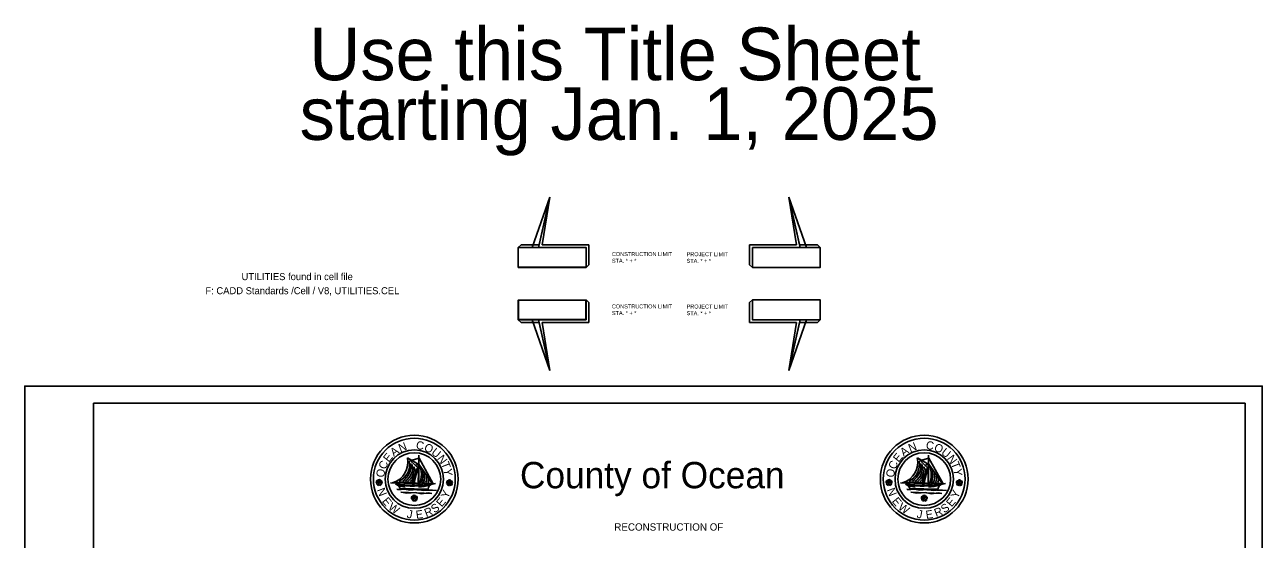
# Model space of a CAD drawing. Extents: x -51896 to -50062, y 9316 to 10514.
# Drawn here: x -51896 to -50816, y 10064 to 10514 of the extents above; entities that cross this region are included whole.
import ezdxf

# ---------------------------------------------------------------- set-up
doc = ezdxf.new("R2010")
doc.units = 0
for name, color, linetype in [('_Guidelines', 7, 'Continuous'), ('Level 1', 7, 'Continuous'), ('Level 47', 7, 'Continuous'), ('Level 60', 7, 'Continuous')]:
    doc.layers.add(name, color=color, linetype=linetype)

msp = doc.modelspace()

# ---------------------------------------------------------------- linework, layer by layer
at = {"layer": '_Guidelines'}
msp.add_lwpolyline([(-51895.6, 9478.3), (-50815.6, 9478.3), (-50815.6, 10198.3), (-51895.6, 10198.3)], close=True, dxfattribs=at)
at = {"layer": 'Level 1'}
for p, q in [((-51452.8, 10319.3), (-51437.3, 10363.4)), ((-51437.3, 10363.4), (-51447.3, 10319.3)), ((-51437.3, 10363.4), (-51446.7, 10321.7)), ((-51444, 10321.7), (-51437.3, 10363.4)), ((-51222.2, 10321.7), (-51228.9, 10363.4)), ((-51228.9, 10363.4), (-51219.5, 10321.7)), ((-51213.4, 10319.3), (-51228.9, 10363.4)), ((-51228.9, 10363.4), (-51218.9, 10319.3)), ((-51462.4, 10321.7), (-51464.9, 10319.3)), ((-51464.9, 10319.3), (-51405.6, 10319.3)), ((-51446.7, 10321.7), (-51462.4, 10321.7)), ((-51447.3, 10319.3), (-51452.8, 10319.3)), ((-51403.2, 10321.7), (-51444, 10321.7)), ((-51405.6, 10319.3), (-51405.6, 10301.9)), ((-51403.2, 10304.3), (-51403.2, 10321.7)), ((-51263.1, 10304.3), (-51263.1, 10321.7)), ((-51263.1, 10321.7), (-51222.2, 10321.7)), ((-51201.3, 10319.3), (-51260.6, 10319.3)), ((-51260.6, 10319.3), (-51260.6, 10301.9)), ((-51219.5, 10321.7), (-51203.8, 10321.7)), ((-51218.9, 10319.3), (-51213.4, 10319.3)), ((-51203.8, 10321.7), (-51201.3, 10319.3)), ((-51405.6, 10301.9), (-51403.2, 10304.3)), ((-51260.6, 10301.9), (-51263.1, 10304.3)), ((-51405.6, 10273.6), (-51403.2, 10271.2)), ((-51405.6, 10256.2), (-51405.6, 10273.6)), ((-51403.2, 10271.2), (-51403.2, 10253.7)), ((-51260.6, 10273.6), (-51263.1, 10271.2)), ((-51263.1, 10271.2), (-51263.1, 10253.7)), ((-51260.6, 10256.2), (-51260.6, 10273.6)), ((-51462.4, 10253.7), (-51464.9, 10256.2)), ((-51464.9, 10256.2), (-51405.6, 10256.2)), ((-51446.7, 10253.7), (-51462.4, 10253.7)), ((-51447.3, 10256.2), (-51452.8, 10256.2)), ((-51452.8, 10256.2), (-51437.3, 10212)), ((-51437.3, 10212), (-51447.3, 10256.2)), ((-51437.3, 10212), (-51446.7, 10253.7)), ((-51403.2, 10253.7), (-51444, 10253.7)), ((-51444, 10253.7), (-51437.3, 10212)), ((-51263.1, 10253.7), (-51222.2, 10253.7)), ((-51201.3, 10256.2), (-51260.6, 10256.2)), ((-51213.4, 10256.2), (-51228.9, 10212)), ((-51228.9, 10212), (-51218.9, 10256.2)), ((-51222.2, 10253.7), (-51228.9, 10212)), ((-51228.9, 10212), (-51219.5, 10253.7)), ((-51219.5, 10253.7), (-51203.8, 10253.7)), ((-51218.9, 10256.2), (-51213.4, 10256.2)), ((-51203.8, 10253.7), (-51201.3, 10256.2))]:
    msp.add_line(p, q, dxfattribs=at)
for points in [[(-51464.9, 10319.3), (-51405.6, 10319.3), (-51405.6, 10302), (-51464.9, 10302)], [(-51464.9, 10319.3), (-51405.6, 10319.3), (-51405.6, 10301.9), (-51464.9, 10301.9)], [(-51260.6, 10319.3), (-51201.3, 10319.3), (-51201.3, 10301.9), (-51260.6, 10301.9)], [(-51260.6, 10319.3), (-51201.3, 10319.3), (-51201.3, 10301.9), (-51260.6, 10301.9)], [(-51405.8, 10273.4), (-51464.9, 10273.4), (-51464.9, 10256.2), (-51405.8, 10256.2)], [(-51464.7, 10273.4), (-51405.8, 10273.4), (-51405.8, 10256.4), (-51464.7, 10256.4)], [(-51260.6, 10273.6), (-51201.3, 10273.6), (-51201.3, 10256.2), (-51260.6, 10256.2)], [(-51260.6, 10273.6), (-51201.3, 10273.6), (-51201.3, 10256.2), (-51260.6, 10256.2)], [(-51835.6, 10183.3), (-50830.6, 10183.3), (-50830.6, 9493.3), (-51835.6, 9493.3)]]:
    msp.add_lwpolyline(points, close=True, dxfattribs=at)
at = {"layer": 'Level 47'}
for p, q in [((-51561.6, 10135.7), (-51552.4, 10126.6)), ((-51561.6, 10135.7), (-51551.6, 10129.8)), ((-51551.5, 10135.2), (-51558.8, 10133.2)), ((-51551.8, 10137.6), (-51552.2, 10111.8)), ((-51551.8, 10137.8), (-51551.8, 10112.4)), ((-51551.5, 10135.2), (-51539.2, 10112.9)), ((-51116.6, 10135.7), (-51107.4, 10126.6)), ((-51116.6, 10135.7), (-51106.6, 10129.8)), ((-51106.5, 10135.2), (-51113.8, 10133.2)), ((-51106.8, 10137.6), (-51107.2, 10111.8)), ((-51106.8, 10137.8), (-51106.8, 10112.4)), ((-51106.5, 10135.2), (-51094.2, 10112.9)), ((-51552.4, 10126.6), (-51557.5, 10113.9)), ((-51551.6, 10129.8), (-51557.1, 10111.6)), ((-51551.6, 10129.8), (-51556.3, 10111.7)), ((-51551.7, 10130.2), (-51554.4, 10129.3)), ((-51551.7, 10130.2), (-51539.7, 10113)), ((-51107.4, 10126.6), (-51112.5, 10113.9)), ((-51106.6, 10129.8), (-51112.1, 10111.6)), ((-51106.6, 10129.8), (-51111.3, 10111.7)), ((-51106.7, 10130.2), (-51109.4, 10129.3)), ((-51106.7, 10130.2), (-51094.7, 10113)), ((-51576.3, 10113.8), (-51553.4, 10113.1)), ((-51575, 10113.9), (-51552.1, 10113.2)), ((-51574.5, 10113.8), (-51551.7, 10113.2)), ((-51537.1, 10113.3), (-51540.8, 10112.4)), ((-51539.2, 10112.9), (-51537.1, 10113.3)), ((-51131.3, 10113.8), (-51108.4, 10113.1)), ((-51130, 10113.9), (-51107.1, 10113.2)), ((-51129.5, 10113.8), (-51106.7, 10113.2)), ((-51092.1, 10113.3), (-51095.8, 10112.4)), ((-51094.2, 10112.9), (-51092.1, 10113.3)), ((-51570.9, 10108.1), (-51536.3, 10107)), ((-51564.3, 10108.3), (-51570.1, 10107.7)), ((-51567.9, 10108.8), (-51543.6, 10108.3)), ((-51567.3, 10105.5), (-51540.3, 10104.5)), ((-51562.2, 10104.8), (-51567.1, 10105.5)), ((-51559.4, 10107.4), (-51564.3, 10108.3)), ((-51554.6, 10105.3), (-51562.2, 10104.8)), ((-51553.3, 10107.9), (-51559.4, 10107.4)), ((-51549.6, 10104.3), (-51554.6, 10105.3)), ((-51547.4, 10107), (-51553.3, 10107.9)), ((-51543.1, 10105.1), (-51549.6, 10104.3)), ((-51543.1, 10107.6), (-51547.4, 10107)), ((-51536.3, 10107), (-51543.1, 10107.6)), ((-51540.3, 10104.5), (-51543.1, 10105.1)), ((-51125.9, 10108.1), (-51091.3, 10107)), ((-51119.3, 10108.3), (-51125.1, 10107.7)), ((-51122.9, 10108.8), (-51098.6, 10108.3)), ((-51122.3, 10105.5), (-51095.3, 10104.5)), ((-51117.2, 10104.8), (-51122.1, 10105.5)), ((-51114.4, 10107.4), (-51119.3, 10108.3)), ((-51109.6, 10105.3), (-51117.2, 10104.8)), ((-51108.3, 10107.9), (-51114.4, 10107.4)), ((-51104.6, 10104.3), (-51109.6, 10105.3)), ((-51102.4, 10107), (-51108.3, 10107.9)), ((-51098.1, 10105.1), (-51104.6, 10104.3)), ((-51098.1, 10107.6), (-51102.4, 10107)), ((-51091.3, 10107), (-51098.1, 10107.6)), ((-51095.3, 10104.5), (-51098.1, 10105.1))]:
    msp.add_line(p, q, dxfattribs=at)
for centre, radius in [((-51555.6, 10117), 38.3), ((-51555.6, 10117), 35.7), ((-51110.6, 10117), 38.3), ((-51110.6, 10117), 35.7), ((-51555.6, 10117), 25.5), ((-51110.6, 10117), 25.5), ((-51555.6, 10117), 23), ((-51110.6, 10117), 23), ((-51586.3, 10114.1), 0.636), ((-51524.9, 10113.9), 0.636), ((-51141.3, 10114.1), 0.636), ((-51079.9, 10113.9), 0.636), ((-51555.6, 10100.4), 0.636), ((-51110.6, 10100.4), 0.636)]:
    msp.add_circle(centre, radius, dxfattribs=at)
for centre, radius, start, end in [((-51579.8, 10131.7), 18.6, 286.3982, 12.5583), ((-51575.6, 10129.5), 15.8, 295.7136, 11.9837), ((-51574.4, 10128.7), 15.9, 302.8177, 7.3857), ((-51134.8, 10131.7), 18.6, 286.3982, 12.5583), ((-51130.6, 10129.5), 15.8, 295.7136, 11.9837), ((-51129.4, 10128.7), 15.9, 302.8177, 7.3857), ((-51571.1, 10126.8), 13.9, 303.4117, 11.8432), ((-51569.9, 10126.2), 14.2, 308.0904, 6.7516), ((-51569.4, 10126.3), 15.3, 312.3822, 0.1337), ((-51569.6, 10120.9), 20.2, 334.4057, 27.4437), ((-51569.9, 10120.6), 21.7, 342.0095, 10.6368), ((-51562.6, 10119.5), 16, 338.8817, 9.0123), ((-51554.8, 10117.8), 9.91, 340.1271, 10.8132), ((-51126.1, 10126.8), 13.9, 303.4117, 11.8432), ((-51124.9, 10126.2), 14.2, 308.0904, 6.7516), ((-51124.4, 10126.3), 15.3, 312.3822, 0.1337), ((-51124.6, 10120.9), 20.2, 334.4057, 27.4437), ((-51124.9, 10120.6), 21.7, 342.0095, 10.6368), ((-51117.6, 10119.5), 16, 338.8817, 9.0123), ((-51109.8, 10117.8), 9.91, 340.1271, 10.8132), ((-51586.7, 10114.2), 2.14, 133.9141, 192.1736), ((-51588.5, 10114), 0.469, 220.4586, 329.0933), ((-51588, 10112.8), 0.485, 79.0255, 179.7037), ((-51586.6, 10113.7), 2.14, 205.9141, 264.1736), ((-51588.1, 10115.3), 0.485, 7.0255, 107.7037), ((-51586, 10114), 2.13, 140.5851, 184.6722), ((-51586.1, 10114.4), 2.13, 212.5851, 256.6722), ((-51587, 10116.1), 0.469, 148.4586, 257.0933), ((-51586.3, 10114.5), 2.14, 61.9141, 120.1736), ((-51586.3, 10113.7), 2.13, 68.5851, 112.6722), ((-51587, 10112), 0.469, 292.4586, 41.0933), ((-51585.6, 10112.1), 0.485, 151.0255, 251.7037), ((-51586.6, 10114.3), 2.13, 284.5851, 328.6722), ((-51586, 10113.7), 2.14, 277.9141, 336.1736), ((-51585.7, 10116.1), 0.485, 295.0255, 35.7037), ((-51584.6, 10115.4), 0.469, 76.4586, 185.0933), ((-51586.7, 10113.9), 2.13, 356.5851, 40.6722), ((-51584.5, 10112.8), 0.469, 4.4586, 113.0933), ((-51585.9, 10114.2), 2.14, 349.9141, 48.1736), ((-51584.2, 10114.1), 0.485, 223.0255, 323.7037), ((-51565, 10046.8), 67.7, 79.1158, 98.0807), ((-51556.7, 10232.1), 120.4, 262.7264, 278.3635), ((-51573.7, 10106.8), 6.03, 18.5089, 73.3259), ((-51557.1, 10202.1), 91.2, 261.8575, 280.0622), ((-51557.6, 10168.3), 58.5, 258.4018, 264.167), ((-51554.8, 10166.1), 56, 272.9459, 283.1385), ((-51544.3, 10095.8), 17.8, 75.1755, 113.4836), ((-51547.5, 10116.5), 4.38, 332.6534, 15.6069), ((-51538.5, 10107.8), 5.15, 97.5209, 175.2261), ((-51525.3, 10114), 2.14, 133.9141, 192.1736), ((-51527.1, 10113.9), 0.469, 220.4586, 329.0933), ((-51526.6, 10112.6), 0.485, 79.0255, 179.7037), ((-51525.2, 10113.5), 2.14, 205.9141, 264.1736), ((-51526.7, 10115.1), 0.485, 7.0255, 107.7037), ((-51524.6, 10113.8), 2.13, 140.5851, 184.6722), ((-51524.7, 10114.2), 2.13, 212.5851, 256.6722), ((-51525.6, 10115.9), 0.469, 148.4586, 257.0933), ((-51524.9, 10114.3), 2.14, 61.9141, 120.1736), ((-51524.9, 10113.5), 2.13, 68.5851, 112.6722), ((-51525.6, 10111.8), 0.469, 292.4586, 41.0933), ((-51524.2, 10111.9), 0.485, 151.0255, 251.7037), ((-51525.2, 10114.2), 2.13, 284.5851, 328.6722), ((-51524.6, 10113.5), 2.14, 277.9141, 336.1736), ((-51524.3, 10115.9), 0.485, 295.0255, 35.7037), ((-51523.2, 10115.2), 0.469, 76.4586, 185.0933), ((-51525.3, 10113.8), 2.13, 356.5851, 40.6722), ((-51523.1, 10112.6), 0.469, 4.4586, 113.0933), ((-51524.5, 10114), 2.14, 349.9141, 48.1736), ((-51522.8, 10114), 0.485, 223.0255, 323.7037), ((-51141.7, 10114.2), 2.14, 133.9141, 192.1736), ((-51143.5, 10114), 0.469, 220.4586, 329.0933), ((-51143, 10112.8), 0.485, 79.0255, 179.7037), ((-51141.6, 10113.7), 2.14, 205.9141, 264.1736), ((-51143.1, 10115.3), 0.485, 7.0255, 107.7037), ((-51141, 10114), 2.13, 140.5851, 184.6722), ((-51141.1, 10114.4), 2.13, 212.5851, 256.6722), ((-51142, 10116.1), 0.469, 148.4586, 257.0933), ((-51141.3, 10114.5), 2.14, 61.9141, 120.1736), ((-51141.3, 10113.7), 2.13, 68.5851, 112.6722), ((-51142, 10112), 0.469, 292.4586, 41.0933), ((-51140.6, 10112.1), 0.485, 151.0255, 251.7037), ((-51141.6, 10114.3), 2.13, 284.5851, 328.6722), ((-51141, 10113.7), 2.14, 277.9141, 336.1736), ((-51140.7, 10116.1), 0.485, 295.0255, 35.7037), ((-51139.6, 10115.4), 0.469, 76.4586, 185.0933), ((-51141.7, 10113.9), 2.13, 356.5851, 40.6722), ((-51139.5, 10112.8), 0.469, 4.4586, 113.0933), ((-51140.9, 10114.2), 2.14, 349.9141, 48.1736), ((-51139.2, 10114.1), 0.485, 223.0255, 323.7037), ((-51120, 10046.8), 67.7, 79.1158, 98.0807), ((-51111.7, 10232.1), 120.4, 262.7264, 278.3635), ((-51128.7, 10106.8), 6.03, 18.5089, 73.3259), ((-51112.1, 10202.1), 91.2, 261.8575, 280.0622), ((-51112.6, 10168.3), 58.5, 258.4018, 264.167), ((-51109.8, 10166.1), 56, 272.9459, 283.1385), ((-51099.3, 10095.8), 17.8, 75.1755, 113.4836), ((-51102.5, 10116.5), 4.38, 332.6534, 15.6069), ((-51093.5, 10107.8), 5.15, 97.5209, 175.2261), ((-51080.3, 10114), 2.14, 133.9141, 192.1736), ((-51082.1, 10113.9), 0.469, 220.4586, 329.0933), ((-51081.6, 10112.6), 0.485, 79.0255, 179.7037), ((-51080.2, 10113.5), 2.14, 205.9141, 264.1736), ((-51081.7, 10115.1), 0.485, 7.0255, 107.7037), ((-51079.6, 10113.8), 2.13, 140.5851, 184.6722), ((-51079.7, 10114.2), 2.13, 212.5851, 256.6722), ((-51080.6, 10115.9), 0.469, 148.4586, 257.0933), ((-51079.9, 10114.3), 2.14, 61.9141, 120.1736), ((-51079.9, 10113.5), 2.13, 68.5851, 112.6722), ((-51080.6, 10111.8), 0.469, 292.4586, 41.0933), ((-51079.2, 10111.9), 0.485, 151.0255, 251.7037), ((-51080.2, 10114.2), 2.13, 284.5851, 328.6722), ((-51079.6, 10113.5), 2.14, 277.9141, 336.1736), ((-51079.3, 10115.9), 0.485, 295.0255, 35.7037), ((-51078.2, 10115.2), 0.469, 76.4586, 185.0933), ((-51080.3, 10113.8), 2.13, 356.5851, 40.6722), ((-51078.1, 10112.6), 0.469, 4.4586, 113.0933), ((-51079.5, 10114), 2.14, 349.9141, 48.1736), ((-51077.8, 10114), 0.485, 223.0255, 323.7037), ((-51556, 10100.5), 2.14, 133.9141, 192.1736), ((-51557.8, 10100.3), 0.469, 220.4586, 329.0933), ((-51557.3, 10099.1), 0.485, 79.0255, 179.7037), ((-51555.8, 10100), 2.14, 205.9141, 264.1736), ((-51557.4, 10101.6), 0.485, 7.0255, 107.7037), ((-51555.2, 10100.3), 2.13, 140.5851, 184.6722), ((-51555.4, 10100.7), 2.13, 212.5851, 256.6722), ((-51555.6, 10100.8), 2.14, 61.9141, 120.1736), ((-51556.3, 10102.4), 0.469, 148.4586, 257.0933), ((-51555.6, 10100), 2.13, 68.5851, 112.6722), ((-51556.2, 10098.3), 0.469, 292.4586, 41.0933), ((-51554.9, 10098.3), 0.485, 151.0255, 251.7037), ((-51555.8, 10100.6), 2.13, 284.5851, 328.6722), ((-51555.3, 10100), 2.14, 277.9141, 336.1736), ((-51555, 10102.4), 0.485, 295.0255, 35.7037), ((-51553.8, 10101.7), 0.469, 76.4586, 185.0933), ((-51555.9, 10100.2), 2.13, 356.5851, 40.6722), ((-51553.8, 10099.1), 0.469, 4.4586, 113.0933), ((-51553.5, 10100.4), 0.485, 223.0255, 323.7037), ((-51555.2, 10100.5), 2.14, 349.9141, 48.1736), ((-51111, 10100.5), 2.14, 133.9141, 192.1736), ((-51112.8, 10100.3), 0.469, 220.4586, 329.0933), ((-51112.3, 10099.1), 0.485, 79.0255, 179.7037), ((-51110.8, 10100), 2.14, 205.9141, 264.1736), ((-51112.4, 10101.6), 0.485, 7.0255, 107.7037), ((-51110.2, 10100.3), 2.13, 140.5851, 184.6722), ((-51110.4, 10100.7), 2.13, 212.5851, 256.6722), ((-51110.6, 10100.8), 2.14, 61.9141, 120.1736), ((-51111.3, 10102.4), 0.469, 148.4586, 257.0933), ((-51110.6, 10100), 2.13, 68.5851, 112.6722), ((-51111.2, 10098.3), 0.469, 292.4586, 41.0933), ((-51109.9, 10098.3), 0.485, 151.0255, 251.7037), ((-51110.8, 10100.6), 2.13, 284.5851, 328.6722), ((-51110.3, 10100), 2.14, 277.9141, 336.1736), ((-51110, 10102.4), 0.485, 295.0255, 35.7037), ((-51108.8, 10101.7), 0.469, 76.4586, 185.0933), ((-51110.9, 10100.2), 2.13, 356.5851, 40.6722), ((-51108.8, 10099.1), 0.469, 4.4586, 113.0933), ((-51108.5, 10100.4), 0.485, 223.0255, 323.7037), ((-51110.2, 10100.5), 2.14, 349.9141, 48.1736)]:
    msp.add_arc(centre, radius, start, end, dxfattribs=at)
at = {"layer": 'Level 60'}
msp.add_line((-51260.6, 10256.2), (-51201.3, 10256.2), dxfattribs=at)

# ---------------------------------------------------------------- texts
at = {"layer": 'Level 1'}
for s, height, p in [('Use this Title Sheet', 46.017, (-51647.2, 10465.4)), ('starting Jan. 1, 2025', 46.017, (-51655.7, 10413.3)), ('CONSTRUCTION LIMIT', 3.5, (-51383.2, 10311.8)), ('PROJECT LIMIT', 3.5, (-51318, 10311.7)), ('STA. * + * ', 3.5, (-51383.2, 10306)), ('STA. * + *', 3.5, (-51318, 10305.9)), ('UTILITIES found in cell file', 6.136, (-51706.4, 10290.8)), ('F: CADD Standards /Cell / V8, UTILITIES.CEL', 6.136, (-51737.9, 10278.5)), ('CONSTRUCTION LIMIT', 3.5, (-51383.2, 10266.1)), ('STA. * + *', 3.5, (-51383.2, 10260.3)), ('STA. * + *', 3.5, (-51318, 10260.2)), ('PROJECT LIMIT', 3.5, (-51318, 10266)), ('County of Ocean', 23.009, (-51463.4, 10109)), ('RECONSTRUCTION OF', 6.405, (-51381.1, 10072))]:
    msp.add_text(s, height=height, dxfattribs=at).set_placement(p)
at = {"layer": 'Level 47'}
for s, rotation, p in [('A', 36.3513, (-51573.5, 10136.5)), ('N', 21.3513, (-51567.8, 10140.4)), ('C', 351.3513, (-51554.5, 10143.4)), ('O', 336.3513, (-51547.7, 10142.2)), ('U', 321.3513, (-51541.4, 10139.3)), ('A', 36.3513, (-51128.5, 10136.5)), ('N', 21.3513, (-51122.8, 10140.4)), ('C', 351.3513, (-51109.5, 10143.4)), ('O', 336.3513, (-51102.7, 10142.2)), ('U', 321.3513, (-51096.4, 10139.3)), ('C', 66.3513, (-51580.8, 10124.9)), ('E', 51.3513, (-51577.9, 10131.2)), ('N', 306.3513, (-51536.1, 10134.9)), ('T', 291.3513, (-51532.4, 10130.6)), ('C', 66.3513, (-51135.8, 10124.9)), ('E', 51.3513, (-51132.9, 10131.2)), ('N', 306.3513, (-51091.1, 10134.9)), ('T', 291.3513, (-51087.4, 10130.6)), ('O', 81.3513, (-51582, 10118.1)), ('Y', 276.3513, (-51530, 10125.8)), ('O', 81.3513, (-51137, 10118.1)), ('Y', 276.3513, (-51085, 10125.8)), ('N', 111.3513, (-51579.2, 10103.9)), ('N', 111.3513, (-51134.2, 10103.9)), ('E', 308.8868, (-51584.2, 10097.6)), ('E', 50.2377, (-51531.7, 10092.2)), ('Y', 66.2586, (-51526.3, 10099.5)), ('E', 308.8868, (-51139.2, 10097.6)), ('E', 50.2377, (-51086.7, 10092.2)), ('Y', 66.2586, (-51081.3, 10099.5)), ('W', 324.4623, (-51579, 10091.2)), ('J', 349.6058, (-51562.5, 10083.3)), ('E', 8.2035, (-51553.8, 10082.2)), ('R', 21.5711, (-51545.2, 10083.8)), ('S', 35.2637, (-51538, 10087)), ('W', 324.4623, (-51134, 10091.2)), ('J', 349.6058, (-51117.5, 10083.3)), ('E', 8.2035, (-51108.8, 10082.2)), ('R', 21.5711, (-51100.2, 10083.8)), ('S', 35.2637, (-51093, 10087))]:
    msp.add_text(s, height=7.15, rotation=rotation, dxfattribs=at).set_placement(p)

doc.saveas('drawing.dxf')
